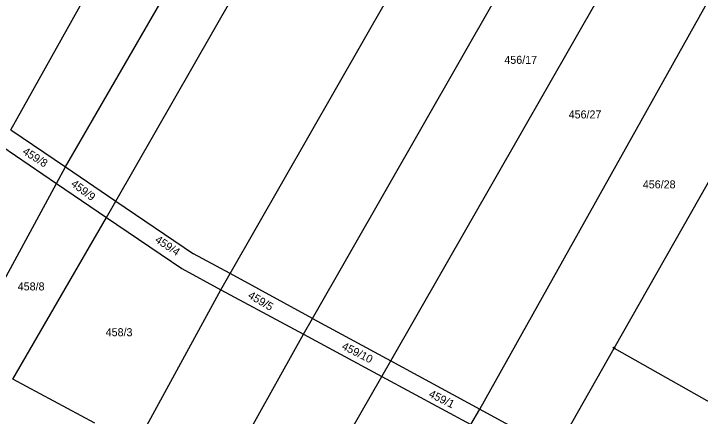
# Model space of a CAD drawing. Extents: x -634640 to -629202, y -1196156 to -1190068.
# Drawn here: x -631739 to -631593.2, y -1192334.4 to -1192249 of the extents above; entities that cross this region are included whole.
import ezdxf

# ---------------------------------------------------------------- set-up
doc = ezdxf.new("R2010")
doc.units = 0
for name, color, linetype in [('Vrstva 1', 7, 'Continuous'), ('Vrstva 2', 7, 'Continuous'), ('Vrstva 8', 7, 'Continuous')]:
    doc.layers.add(name, color=color, linetype=linetype)

msp = doc.modelspace()

# ---------------------------------------------------------------- linework, layer by layer
at = {"layer": 'Vrstva 1'}
for p, q in [((-631693.06, -1192304.14), (-631595.57, -1192133.92)), ((-631675.56, -1192313.63), (-631587.16, -1192159.23)), ((-631658.94, -1192322.64), (-631579.36, -1192183.61)), ((-631739.56, -1192273.61), (-631693.54, -1192191.04)), ((-631728, -1192281.47), (-631680.08, -1192198.79)), ((-631717.27, -1192288.76), (-631669.34, -1192204.98)), ((-631640.07, -1192332.88), (-631571.15, -1192209.8)), ((-631611.53, -1192319.92), (-631563.25, -1192234.99)), ((-631739.56, -1192273.61), (-631728, -1192281.47)), ((-631741.52, -1192277.11), (-631729.91, -1192285)), ((-631729.91, -1192285), (-631728, -1192281.47)), ((-631728, -1192281.47), (-631717.27, -1192288.76)), ((-631749.63, -1192321.4), (-631729.91, -1192285)), ((-631729.91, -1192285), (-631719.28, -1192292.22)), ((-631719.28, -1192292.22), (-631717.27, -1192288.76)), ((-631717.27, -1192288.76), (-631700.84, -1192299.92)), ((-631739.13, -1192326.55), (-631719.28, -1192292.22)), ((-631719.28, -1192292.22), (-631703.3, -1192303.08)), ((-631693.06, -1192304.14), (-631700.84, -1192299.92)), ((-631703.3, -1192303.08), (-631695.01, -1192307.55)), ((-631695.01, -1192307.55), (-631693.06, -1192304.14)), ((-631675.56, -1192313.63), (-631693.06, -1192304.14)), ((-631728.29, -1192368.62), (-631695.01, -1192307.55)), ((-631695.01, -1192307.55), (-631677.49, -1192317)), ((-631677.49, -1192317), (-631675.56, -1192313.63)), ((-631675.56, -1192313.63), (-631658.94, -1192322.64)), ((-631718.14, -1192389.69), (-631677.49, -1192317)), ((-631677.49, -1192317), (-631660.85, -1192325.98)), ((-631623.88, -1192341.65), (-631611.53, -1192319.92)), ((-631660.85, -1192325.98), (-631658.94, -1192322.64)), ((-631658.94, -1192322.64), (-631640.07, -1192332.88)), ((-631721.73, -1192335.89), (-631739.13, -1192326.55)), ((-631699.56, -1192393.62), (-631660.85, -1192325.98)), ((-631660.85, -1192325.98), (-631641.92, -1192336.19)), ((-631641.92, -1192336.19), (-631640.07, -1192332.88)), ((-631640.07, -1192332.88), (-631624.58, -1192341.28))]:
    msp.add_line(p, q, dxfattribs=at)
msp.add_lwpolyline([(-631611.53, -1192319.92), (-631588.62, -1192332.93), (-631552.68, -1192268.74)], dxfattribs=at)
at = {"layer": 'Vrstva 8'}
msp.add_lwpolyline([(-631611.44, -1192319.77), (-631611.35, -1192319.92), (-631611.44, -1192320.07), (-631611.62, -1192320.07), (-631611.71, -1192319.92), (-631611.62, -1192319.77), (-631611.44, -1192319.77)], dxfattribs=at)

# ---------------------------------------------------------------- texts
at = {"layer": 'Vrstva 2'}
for s, p in [('456/17', (-631634.833, -1192259.61)), ('456/27', (-631621.183, -1192271.19)), ('456/28', (-631605.443, -1192286.04)), ('458/8', (-631738.123, -1192307.7)), ('458/3', (-631719.453, -1192317.42))]:
    msp.add_text(s, height=1.7, dxfattribs=at).set_placement(p)
for s, rotation, p in [('459/8', 327.61727, (-631737.25, -1192278.617)), ('459/9', 322.97631, (-631726.98, -1192285.383)), ('459/4', 326.70054, (-631709.142, -1192297.34)), ('459/5', 329.22155, (-631689.406, -1192309.191)), ('459/10', 333.00307, (-631669.508, -1192320.068)), ('459/1', 333.46144, (-631651.038, -1192330.216))]:
    msp.add_text(s, height=1.7, rotation=rotation, dxfattribs=at).set_placement(p)

doc.saveas('drawing.dxf')
